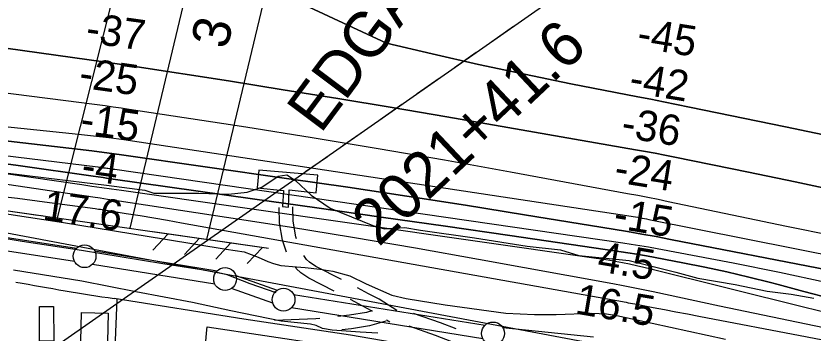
# Model space of a CAD drawing. Extents: x 3508733 to 3546731, y 546897 to 572481.
# Drawn here: x 3525316 to 3527070, y 563035 to 563733 of the extents above; entities that cross this region are included whole.
import ezdxf

# ---------------------------------------------------------------- set-up
doc = ezdxf.new("R2010")
doc.units = 0
for name, color, linetype in [('V-BLDG-OTLN', 7, 'Continuous'), ('V-CHAN-DOCK', 7, 'Continuous'), ('V-FLOD-BASE', 7, 'Continuous'), ('V-LEVE-TOET', 7, 'Continuous'), ('V-RIVR-EDGE', 7, 'Continuous'), ('V-RIVR-FERY', 7, 'Continuous'), ('V-RIVR-RANG', 7, 'Continuous'), ('V-ROAD-CNTR', 7, 'Continuous'), ('V-RRAP-FSHR', 7, 'Continuous'), ('V-SITE-OTLN', 7, 'Continuous'), ('V-SURV-IDEN', 7, 'Continuous'), ('V-SURV-LINE', 7, 'Continuous'), ('V-TOPO-DPTH', 7, 'Continuous'), ('V-TOPO-GNAM-IDEN', 7, 'Continuous'), ('V-TOPO-MINR', 7, 'Continuous'), ('V-TOPO-WATR', 7, 'Continuous'), ('V-UTIL-IDEN', 7, 'Continuous'), ('V-UTIL-LINE', 7, 'Continuous')]:
    doc.layers.add(name, color=color, linetype=linetype)

msp = doc.modelspace()

# ---------------------------------------------------------------- linework, layer by layer
at = {"layer": 'V-BLDG-OTLN'}
for points in [[(3525398.1, 563093.9), (3525398.9, 563017.6), (3525367.5, 563017.3), (3525367.4, 563093.6)], [(3525456.8, 562955.1), (3525459.9, 563080.7), (3525518.7, 563079.2), (3525515.6, 562953.7)]]:
    msp.add_lwpolyline(points, close=True, dxfattribs=at)
at = {"layer": 'V-CHAN-DOCK'}
msp.add_lwpolyline([(3525915.3, 563312), (3525917, 563349.9), (3525976.6, 563344), (3525979.8, 563382.7), (3525850.4, 563393.2), (3525846.2, 563354.7), (3525904.7, 563348.5), (3525902.3, 563313.4), (3525915.3, 563312)], dxfattribs=at)
at = {"layer": 'V-FLOD-BASE'}
msp.add_lwpolyline([(3525888.4, 563123.6), (3525831.1, 563143.4), (3525780.5, 563163.1), (3525761.4, 563168.1), (3525723.8, 563174.6), (3525638.9, 563187.8), (3525459.7, 563217), (3525329, 563236.9), (3525121.1, 563271.2), (3525029.4, 563283.8), (3524899.6, 563302.9)], dxfattribs=at)
at = {"layer": 'V-LEVE-TOET'}
for points in [[(3525222.2, 563308.4), (3525419.9, 563278.3), (3525645, 563241.7), (3525778.4, 563219.8), (3525818.1, 563213.9), (3525848.8, 563201.9), (3525869.9, 563192.8), (3525882.2, 563188.6), (3525898.6, 563183.6), (3525932.9, 563181.2), (3525951.9, 563179.8), (3525984.1, 563176), (3526012.8, 563171.6), (3526050.4, 563161), (3526086.5, 563143.5), (3526142.5, 563118.9), (3526174.6, 563111), (3526260.1, 563097.2), (3526393.6, 563079.3), (3526456.6, 563076), (3526504.5, 563076.2), (3526582.7, 563078.8), (3526615.6, 563077.8), (3526638.1, 563074.1), (3526716.1, 563056.9), (3526877.5, 563021.7)], [(3526111.9, 563035), (3526072.8, 563037.4), (3526011.2, 563041.5), (3525990, 563045.1), (3525976.2, 563051.7), (3525963.9, 563054.5), (3525898.9, 563061.4), (3525788.8, 563084.4), (3525704, 563102.4), (3525579.5, 563125.6), (3525460.5, 563149.4), (3525310, 563173.6)]]:
    msp.add_lwpolyline(points, dxfattribs=at)
at = {"layer": 'V-RIVR-EDGE'}
msp.add_lwpolyline([(3525286.3, 563388.3), (3525381.7, 563376.7), (3525514.9, 563360.8), (3525599.5, 563349.2), (3525619.3, 563343.1), (3525718.4, 563342.9), (3525783.2, 563340.9), (3525824.6, 563345), (3525856.5, 563356.3), (3525892.6, 563380.2), (3525911.8, 563383.2), (3525931, 563370.5), (3525965.1, 563338.6), (3526007.1, 563310.3), (3526101.2, 563271.7), (3526126.4, 563264.4), (3526171.4, 563267.3), (3526206.2, 563261.2), (3526325.1, 563244.7), (3526440.3, 563226.4), (3526514.1, 563218.4), (3526554.3, 563205.7), (3526665.3, 563195.2), (3526767.9, 563169.2), (3526816.5, 563155.8), (3526898.1, 563141.8), (3526968.9, 563127.2), (3527021.7, 563120.5), (3527071.5, 563112)], dxfattribs=at)
at = {"layer": 'V-RIVR-FERY'}
for points in [[(3524970.1, 562704.4), (3528560.1, 565210.4)], [(3526362.7, 563676.5), (3526410.5, 563709.9)], [(3526280.8, 563619.3), (3526328.6, 563652.7)], [(3526198.9, 563562.1), (3526246.7, 563595.5)], [(3526116.9, 563504.9), (3526164.7, 563538.3)], [(3526035, 563447.8), (3526082.8, 563481.1)], [(3525953.1, 563390.6), (3526000.9, 563423.9)]]:
    msp.add_lwpolyline(points, dxfattribs=at)
at = {"layer": 'V-ROAD-CNTR'}
for points in [[(3525911, 563213.4), (3525902.3, 563239.5), (3525895.5, 563278), (3525894.6, 563311.2)], [(3525932.9, 563242.5), (3525931.5, 563246.9), (3525925.4, 563281.1), (3525924.6, 563313)], [(3526032, 563152.8), (3525975.3, 563181.5), (3525961.4, 563191.4), (3525955.1, 563197.3), (3525948.9, 563206.1)], [(3526015.9, 563127.2), (3525959.8, 563155.8), (3525942.4, 563168.1), (3525932.4, 563177.5), (3525931.3, 563179.1)], [(3526154.1, 563085), (3526114.8, 563109.7), (3526091.8, 563121.8), (3526067.5, 563134.5)], [(3527459.7, 562715.9), (3527179.9, 562790), (3527010.3, 562841.2), (3526851.7, 562887.6), (3526669.4, 562923.3), (3526428.3, 562962.7), (3526209.3, 563003.9), (3526051.5, 563030.9), (3525817.1, 563066.2), (3525532, 563111)], [(3525537.4, 563109.3), (3525517.5, 562623.4), (3525505.4, 562185.3), (3525498.9, 562120.6)], [(3526100.6, 563083.1), (3526099.8, 563083.7), (3526077.8, 563095.2), (3526051.5, 563109)], [(3526099.1, 563084.1), (3526087.4, 563080.8), (3526049.5, 563074.5), (3526024.2, 563071.5)], [(3526189.9, 563079.4), (3526248.9, 563058.8), (3526283.7, 563045.2)], [(3525984.6, 563067), (3525975.6, 563066.6), (3525884.7, 563063.1)], [(3526129.8, 563061.6), (3526094, 563051.5), (3526053.7, 563044.8), (3526032.4, 563042.3)], [(3526138.1, 563059.6), (3526131.3, 563063.9)], [(3526180, 563051), (3526238.5, 563030.7), (3526273.9, 563016.8)]]:
    msp.add_lwpolyline(points, dxfattribs=at)
msp.add_arc((3526658.3, 570483.2), 7457.7, 259.62698, 261.31348, dxfattribs=at)
at = {"layer": 'V-RRAP-FSHR'}
for p, q in [((3525373.1, 563293.2), (3525372.8, 563293)), ((3525650.3, 563253.6), (3525616.9, 563217.9)), ((3525719.5, 563243.7), (3525686.2, 563208)), ((3525788.8, 563233.7), (3525755.4, 563198.1)), ((3525858.1, 563223.8), (3525824.7, 563188.2))]:
    msp.add_line(p, q, dxfattribs=at)
for points in [[(3523475.5, 563626.1), (3524086.4, 563502.4), (3525193.3, 563274.6), (3526957.5, 562942.6), (3528202.6, 562690.4), (3529085.9, 562552.3), (3529836.5, 562463.4), (3529988.5, 562444.1), (3530121.4, 562433.3), (3530591.9, 562422.1), (3531229.9, 562384.2)], [(3523966.7, 563480.5), (3524928.8, 563365.8), (3525288.4, 563305.4), (3525871.3, 563221.9)], [(3524485.7, 563418.7), (3524928.8, 563365.8), (3525288.4, 563305.4), (3525363.7, 563294.6)], [(3525616.9, 563258.3), (3525866.8, 563222.6)]]:
    msp.add_lwpolyline(points, dxfattribs=at)
at = {"layer": 'V-SITE-OTLN'}
msp.add_lwpolyline([(3525734.9, 563034.9), (3525736.4, 563048.7), (3525990.5, 563011.1), (3525974.8, 562748.5), (3525958.6, 562369.4), (3525946.9, 562023.8), (3525702.2, 562041.3), (3525708.4, 562249.8), (3525716.8, 562531), (3525714.6, 562786.8)], close=True, dxfattribs=at)
at = {"layer": 'V-SURV-LINE'}
for points in [[(3524948.8, 563299.1), (3525449.1, 563222.1)], [(3525444.5, 563192.5), (3524944.3, 563269.5)], [(3525488.7, 563215.9), (3525758.4, 563172.1)], [(3525753.6, 563142.5), (3525483.9, 563186.3)], [(3525799.5, 563161.6), (3525890.6, 563129.5)], [(3525880.7, 563101.2), (3525789.6, 563133.3)], [(3525926.6, 563120.4), (3526348.1, 563052.4)], [(3526343.3, 563022.8), (3525921.8, 563090.8)], [(3526386.8, 563047.3), (3526586.3, 563026.7)]]:
    msp.add_lwpolyline(points, dxfattribs=at)
for centre in [(3525466.6, 563204.3), (3525775.7, 563154.1), (3525904.5, 563108.8), (3526365.4, 563034.5)]:
    msp.add_circle(centre, 25, dxfattribs=at)
at = {"layer": 'V-TOPO-DPTH'}
for points in [[(3527143, 563460.9), (3527009.1, 563488.9), (3526797.9, 563532.1), (3526769.5, 563537.9), (3526741, 563543.6), (3526712.6, 563549.3), (3526684.1, 563554.9), (3526536.9, 563583.7), (3526435, 563604.4), (3526333.3, 563626), (3526231.9, 563649), (3526130.7, 563672.8), (3525705.6, 563871.2)], [(3527143, 563460.9), (3527009.1, 563488.9), (3526797.9, 563532.1), (3526769.5, 563537.9), (3526741, 563543.6), (3526712.6, 563549.3), (3526684.1, 563554.9), (3526536.9, 563583.7), (3526435, 563604.4), (3526333.3, 563626), (3526231.9, 563649), (3526130.7, 563672.8), (3525705.6, 563871.2)], [(3527132.9, 563346), (3527030.4, 563368), (3526927.8, 563389.4), (3526765.4, 563422.3), (3526743.9, 563426.5), (3526722.4, 563430.7), (3526700.8, 563434.6), (3526679.3, 563438.5), (3526263.8, 563510.5), (3526143.9, 563531), (3526023.9, 563551.1), (3525903.8, 563570.5), (3525783.6, 563589.6), (3525572.8, 563622.3), (3525558, 563624.6), (3525543.1, 563626.8), (3525528.2, 563629), (3525513.4, 563631.1), (3524585.1, 563761)], [(3524585.1, 563761), (3525513.4, 563631.1), (3525528.2, 563629), (3525543.1, 563626.8), (3525558, 563624.6), (3525572.8, 563622.3), (3525783.6, 563589.6), (3525903.8, 563570.5), (3526023.9, 563551.1), (3526143.9, 563531), (3526263.8, 563510.5), (3526679.3, 563438.5), (3526700.8, 563434.6), (3526722.4, 563430.7), (3526743.9, 563426.5), (3526765.4, 563422.3), (3526927.8, 563389.4), (3527030.4, 563368), (3527132.9, 563346)], [(3524831.8, 563622.2), (3525494.6, 563537.8), (3525512.1, 563535.5), (3525529.7, 563533.1), (3525547.2, 563530.6), (3525564.8, 563527.9), (3525821.5, 563488.5), (3525967.3, 563465.4), (3526113, 563441.4), (3526258.4, 563416.2), (3526403.7, 563390), (3526661.5, 563342.5), (3526683.9, 563338.2), (3526706.4, 563333.9), (3526728.8, 563329.4), (3526751.2, 563324.9), (3526909.8, 563291.8), (3527011.4, 563270.7), (3527113.1, 563249.7)], [(3524831.8, 563622.2), (3525494.6, 563537.8), (3525512.1, 563535.5), (3525529.7, 563533.1), (3525547.2, 563530.6), (3525564.8, 563527.9), (3525821.5, 563488.5), (3525967.3, 563465.4), (3526113, 563441.4), (3526258.4, 563416.2), (3526403.7, 563390), (3526661.5, 563342.5), (3526683.9, 563338.2), (3526706.4, 563333.9), (3526728.8, 563329.4), (3526751.2, 563324.9), (3526909.8, 563291.8), (3527011.4, 563270.7), (3527113.1, 563249.7)], [(3524548.4, 563473.7), (3525468.7, 563337.3), (3525484.8, 563334.9), (3525500.9, 563332.5), (3525517, 563330), (3525533.1, 563327.6), (3525778.9, 563290.4), (3525917.8, 563268.8), (3526056.5, 563246.3), (3526195, 563222.6), (3526333.4, 563198.1), (3526629.4, 563144.2), (3526651.6, 563140.1), (3526673.6, 563135.8), (3526695.7, 563131.4), (3526717.7, 563126.8), (3526864, 563095.5), (3526959.2, 563075.4), (3527054.4, 563055.5), (3527149.7, 563036)], [(3527104.6, 563173.4), (3526755.8, 563241.3), (3526724.4, 563247.3), (3526693, 563253), (3526661.5, 563258.5), (3526630, 563263.8), (3526434.5, 563295.5), (3526305.1, 563316.2), (3526175.6, 563336.4), (3526046.1, 563355.8), (3525916.4, 563374.7), (3525548.1, 563427.4), (3525531.7, 563429.7), (3525515.2, 563431.9), (3525498.7, 563434), (3525482.2, 563436), (3525146.2, 563475)], [(3525146.2, 563475), (3525482.2, 563436), (3525498.7, 563434), (3525515.2, 563431.9), (3525531.7, 563429.7), (3525548.1, 563427.4), (3525916.4, 563374.7), (3526046.1, 563355.8), (3526175.6, 563336.4), (3526305.1, 563316.2), (3526434.5, 563295.5), (3526630, 563263.8), (3526661.5, 563258.5), (3526693, 563253), (3526724.4, 563247.3), (3526755.8, 563241.3), (3527104.6, 563173.4)], [(3527106, 563112.2), (3527049.6, 563127), (3526993.2, 563141.8), (3526976.3, 563146.3), (3526928.2, 563158.4), (3526880, 563169.9), (3526831.6, 563180.3), (3526783, 563190), (3526703.5, 563205), (3526694.6, 563206.7), (3526685.6, 563208.2), (3526676.6, 563209.7), (3526667.6, 563211), (3526402.4, 563249.6), (3526260.8, 563270.1), (3526119.2, 563290.5), (3525977.6, 563310.7), (3525835.9, 563330.8), (3525529.5, 563374), (3525518.4, 563375.5), (3525507.3, 563377.1), (3525496.3, 563378.7), (3525485.2, 563380.2), (3525320.3, 563403.6), (3525226.8, 563416.6)], [(3527106, 563112.2), (3527049.6, 563127), (3526993.2, 563141.8), (3526976.3, 563146.3), (3526928.2, 563158.4), (3526880, 563169.9), (3526831.6, 563180.3), (3526783, 563190), (3526703.5, 563205), (3526694.6, 563206.7), (3526685.6, 563208.2), (3526676.6, 563209.7), (3526667.6, 563211), (3526402.4, 563249.6), (3526260.8, 563270.1), (3526119.2, 563290.5), (3525977.6, 563310.7), (3525835.9, 563330.8), (3525529.5, 563374), (3525518.4, 563375.5), (3525507.3, 563377.1), (3525496.3, 563378.7), (3525485.2, 563380.2), (3525320.3, 563403.6), (3525226.8, 563416.6)]]:
    msp.add_lwpolyline(points, dxfattribs=at)
at = {"layer": 'V-TOPO-MINR'}
for points in [[(3525705.6, 563871.2), (3526130.7, 563672.8), (3526231.9, 563649), (3526333.3, 563626), (3526435, 563604.4), (3526536.9, 563583.7), (3526684.1, 563554.9), (3526712.6, 563549.3), (3526741, 563543.6), (3526769.5, 563537.9), (3526797.9, 563532.1), (3527009.1, 563488.9), (3527143, 563460.9)], [(3524585.1, 563761), (3525513.4, 563631.1), (3525528.2, 563629), (3525543.1, 563626.8), (3525558, 563624.6), (3525572.8, 563622.3), (3525783.6, 563589.6), (3525903.8, 563570.5), (3526023.9, 563551.1), (3526143.9, 563531), (3526263.8, 563510.5), (3526679.3, 563438.5), (3526700.8, 563434.6), (3526722.4, 563430.7), (3526743.9, 563426.5), (3526765.4, 563422.3), (3526927.8, 563389.4), (3527030.4, 563368), (3527132.9, 563346)], [(3524831.8, 563622.2), (3525494.6, 563537.8), (3525512.1, 563535.5), (3525529.7, 563533.1), (3525547.2, 563530.6), (3525564.8, 563527.9), (3525821.5, 563488.5), (3525967.3, 563465.4), (3526113, 563441.4), (3526258.4, 563416.2), (3526403.7, 563390), (3526661.5, 563342.5), (3526683.9, 563338.2), (3526706.4, 563333.9), (3526728.8, 563329.4), (3526751.2, 563324.9), (3526909.8, 563291.8), (3527011.4, 563270.7), (3527113.1, 563249.7)], [(3524536.5, 563568.3), (3525453, 563472.9), (3525486.5, 563469.2), (3525520, 563465.2), (3525553.3, 563460.7), (3525586.7, 563455.9), (3526669.2, 563292.4), (3526674.1, 563291.7), (3526679, 563290.9), (3526684, 563290), (3526688.9, 563289.1), (3526693.8, 563288.2), (3526698.7, 563287.3), (3526703.6, 563286.3), (3526708.5, 563285.3), (3527569.1, 563114.2)], [(3524412.2, 563532.8), (3525495.5, 563400.7), (3525498, 563400.4), (3525500.5, 563400), (3525503, 563399.7), (3525505.5, 563399.4), (3525507.9, 563399), (3525510.4, 563398.7), (3525512.9, 563398.3), (3525515.4, 563398), (3525518, 563397.6), (3525521.8, 563397.1), (3525525.5, 563396.6), (3525529.3, 563396), (3525533.1, 563395.5), (3526651, 563233.8), (3526669.9, 563230.9), (3526688.9, 563227.9), (3526707.7, 563224.6), (3526726.6, 563221.1), (3526893.8, 563189.5), (3526996, 563169), (3527097.8, 563147)], [(3524548.4, 563473.7), (3525468.7, 563337.3), (3525484.8, 563334.9), (3525500.9, 563332.5), (3525517, 563330), (3525533.1, 563327.6), (3525778.9, 563290.4), (3525917.8, 563268.8), (3526056.5, 563246.3), (3526195, 563222.6), (3526333.4, 563198.1), (3526629.4, 563144.2), (3526651.6, 563140.1), (3526673.6, 563135.8), (3526695.7, 563131.4), (3526717.7, 563126.8), (3526864, 563095.5), (3526959.2, 563075.4), (3527054.4, 563055.5), (3527149.7, 563036)], [(3525146.2, 563475), (3525482.2, 563436), (3525498.7, 563434), (3525515.2, 563431.9), (3525531.7, 563429.7), (3525548.1, 563427.4), (3525916.4, 563374.7), (3526046.1, 563355.8), (3526175.6, 563336.4), (3526305.1, 563316.2), (3526434.5, 563295.5), (3526630, 563263.8), (3526661.5, 563258.5), (3526693, 563253), (3526724.4, 563247.3), (3526755.8, 563241.3), (3527104.6, 563173.4)], [(3525014, 563426.2), (3525460.5, 563361.8), (3525482.3, 563358.6), (3525504.2, 563355.5), (3525526.1, 563352.3), (3525548, 563349.2), (3526587.4, 563200.8), (3526603.2, 563198.5), (3526618.9, 563196), (3526634.6, 563193.3), (3526650.3, 563190.4), (3526666, 563187.3), (3526681.6, 563184.1), (3526697.1, 563180.5), (3526712.7, 563176.8), (3527051.4, 563092.5), (3527172.9, 563063)], [(3525259.6, 563338.2), (3525319.2, 563331.7), (3525378.6, 563324.2), (3525489.6, 563309.1), (3525493.5, 563308.6), (3525497.4, 563308), (3525501.3, 563307.4), (3525505.2, 563306.8), (3525558.3, 563298.5), (3525588.7, 563293.6), (3525619, 563288.6), (3525649.4, 563283.4), (3525679.7, 563278), (3526658.5, 563102.9), (3526663.2, 563102), (3526667.9, 563101.2), (3526672.6, 563100.3), (3526677.3, 563099.4), (3526718, 563091.7), (3526743.1, 563086.9), (3526768.2, 563082.1), (3526793.2, 563077.3), (3526818.3, 563072.5), (3527772.4, 562890.3)]]:
    msp.add_lwpolyline(points, dxfattribs=at)
at = {"layer": 'V-TOPO-WATR'}
msp.add_lwpolyline([(3525226.8, 563416.6), (3525320.3, 563403.6), (3525485.2, 563380.2), (3525496.3, 563378.7), (3525507.3, 563377.1), (3525518.4, 563375.5), (3525529.5, 563374), (3525835.9, 563330.8), (3525977.6, 563310.7), (3526119.2, 563290.5), (3526260.8, 563270.1), (3526402.4, 563249.6), (3526667.6, 563211), (3526676.6, 563209.7), (3526685.6, 563208.2), (3526694.6, 563206.7), (3526703.5, 563205), (3526783, 563190), (3526831.6, 563180.3), (3526880, 563169.9), (3526928.2, 563158.4), (3526976.3, 563146.3), (3526993.2, 563141.8), (3527049.6, 563127), (3527106, 563112.2)], dxfattribs=at)
at = {"layer": 'V-UTIL-LINE'}
for points in [[(3525407, 563288.4), (3526063.3, 565894.4)], [(3526187.4, 565867.5), (3525566.5, 563265.6)], [(3525736, 563241.3), (3526363.9, 565863)]]:
    msp.add_lwpolyline(points, dxfattribs=at)

# ---------------------------------------------------------------- texts
at = {"layer": 'V-RIVR-RANG'}
for s, rotation, p in [('-37', 351.9879, (3525466.9, 563674.5)), ('-45', 350.7566, (3526679.9, 563663.5)), ('-25', 351.9879, (3525451.9, 563575.6)), ('-42', 350.7566, (3526662.6, 563565)), ('-15', 351.9879, (3525454.5, 563474.3)), ('-36', 350.7566, (3526645.2, 563466.5)), ('-4', 351.9879, (3525457.2, 563372.9)), ('-24', 350.7566, (3526629.7, 563367.7)), ('17.6', 351.7083, (3525372.2, 563284.5)), ('-15', 350.7566, (3526628.2, 563266.7)), ('4.5', 350.4683, (3526592.8, 563171.6)), ('16.5', 350.4683, (3526543.8, 563078.4))]:
    msp.add_text(s, height=67, rotation=rotation, dxfattribs=at).set_placement(p)
at = {"layer": 'V-SURV-IDEN'}
msp.add_text('2021+41.6', height=100, rotation=43.2777, dxfattribs=at).set_placement((3526113.7, 563223.2))
at = {"layer": 'V-TOPO-GNAM-IDEN'}
msp.add_text('EDGARD LDG.', height=100, rotation=53.2245, dxfattribs=at).set_placement((3525986, 563471.8))
at = {"layer": 'V-UTIL-IDEN'}
msp.add_text('3 - 10" GAS P.L.', height=83, rotation=76.3287, dxfattribs=at).set_placement((3525779.8, 563657.3))

doc.saveas('drawing.dxf')
